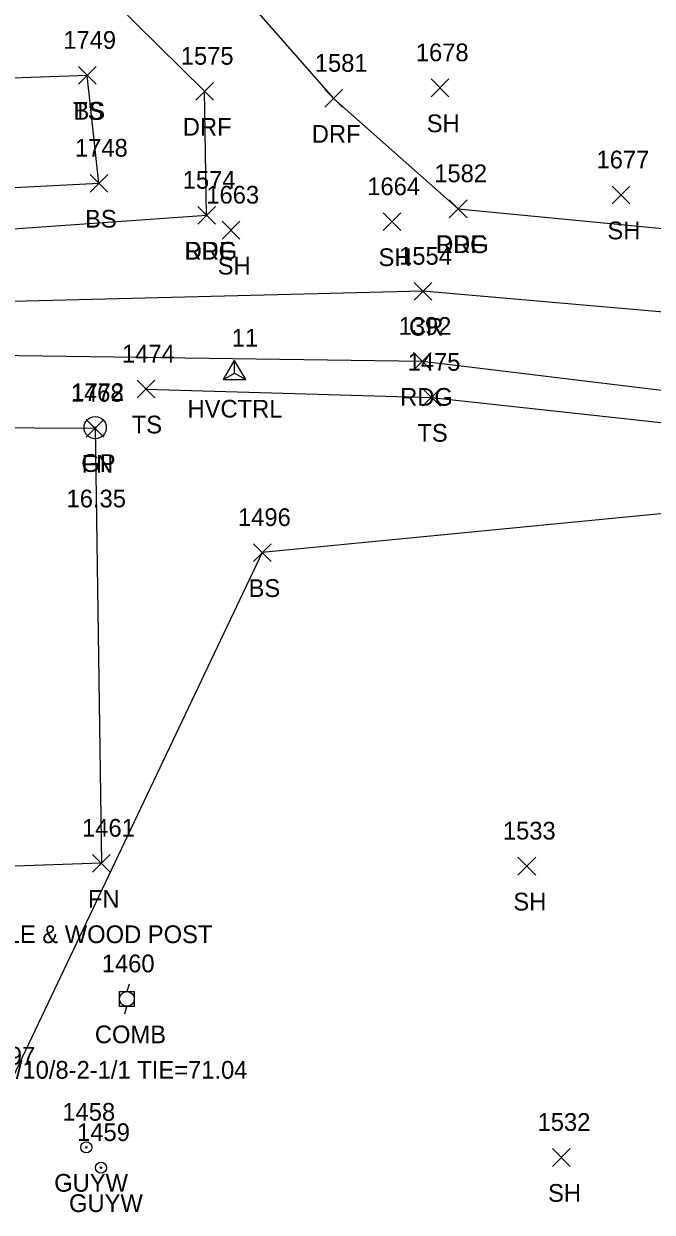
# Model space of a CAD drawing. Extents: x 1609623 to 1616187, y 756677 to 762826.
# Drawn here: x 1610243.7 to 1610314.5, y 761643.7 to 761777.7 of the extents above; entities that cross this region are included whole.
import ezdxf

# ---------------------------------------------------------------- set-up
doc = ezdxf.new("R2010")
doc.units = 0
for name, color, linetype in [('C_A', 7, 'Continuous'), ('C_I', 7, 'Continuous'), ('CPSM', 7, 'Continuous'), ('L_A', 7, 'Continuous'), ('L_C', 7, 'Continuous'), ('L_I', 7, 'Continuous'), ('L_TIC', 7, 'Continuous'), ('LELB', 7, 'Continuous'), ('LFNC', 7, 'Continuous'), ('P_A', 7, 'Continuous'), ('P_I', 7, 'Continuous'), ('P_TIC', 7, 'Continuous'), ('PEU', 7, 'Continuous'), ('PRC', 7, 'Continuous'), ('R_A', 7, 'Continuous'), ('R_C', 7, 'Continuous'), ('R_I', 7, 'Continuous'), ('R_TIC', 7, 'Continuous'), ('RDF', 7, 'Continuous'), ('RGP', 7, 'Continuous'), ('U_A', 7, 'Continuous'), ('U_C', 7, 'Continuous'), ('U_I', 7, 'Continuous'), ('UP', 7, 'Continuous'), ('UPGW', 7, 'Continuous')]:
    doc.layers.add(name, color=color, linetype=linetype)

msp = doc.modelspace()

# ---------------------------------------------------------------- linework, layer by layer
at = {"layer": 'CPSM'}
for p, q in [((1610266.22, 761737.58), (1610267.47, 761739.75)), ((1610268.72, 761737.58), (1610267.47, 761739.75)), ((1610267.47, 761738.3), (1610267.47, 761739.75)), ((1610266.22, 761737.58), (1610267.47, 761738.3)), ((1610267.47, 761738.3), (1610267.47, 761738.3)), ((1610267.47, 761738.3), (1610268.72, 761737.58)), ((1610266.22, 761737.58), (1610268.72, 761737.58))]:
    msp.add_line(p, q, dxfattribs=at)
at = {"layer": 'L_TIC'}
for points in [[(1610249.87, 761770.88), (1610251.87, 761772.88)], [(1610251.87, 761770.88), (1610249.87, 761772.88)], [(1610249.87, 761770.88), (1610251.87, 761772.88)], [(1610251.87, 761770.88), (1610249.87, 761772.88)], [(1610289.62, 761769.48), (1610291.62, 761771.48)], [(1610291.62, 761769.48), (1610289.62, 761771.48)], [(1610251.18, 761758.72), (1610253.18, 761760.72)], [(1610253.18, 761758.72), (1610251.18, 761760.72)], [(1610309.99, 761757.4), (1610311.99, 761759.4)], [(1610311.99, 761757.4), (1610309.99, 761759.4)], [(1610266.07, 761753.43), (1610268.07, 761755.43)], [(1610268.07, 761753.43), (1610266.07, 761755.43)], [(1610284.19, 761754.38), (1610286.19, 761756.38)], [(1610286.19, 761754.38), (1610284.19, 761756.38)], [(1610256.48, 761735.51), (1610258.48, 761737.51)], [(1610258.48, 761735.51), (1610256.48, 761737.51)], [(1610288.65, 761734.58), (1610290.65, 761736.58)], [(1610290.65, 761734.58), (1610288.65, 761736.58)], [(1610250.75, 761731.09), (1610252.75, 761733.09)], [(1610252.75, 761731.09), (1610250.75, 761733.09)], [(1610269.59, 761717.07), (1610271.59, 761719.07)], [(1610271.59, 761717.07), (1610269.59, 761719.07)], [(1610251.46, 761682.04), (1610253.46, 761684.04)], [(1610253.46, 761682.04), (1610251.46, 761684.04)], [(1610299.39, 761681.72), (1610301.39, 761683.72)], [(1610301.39, 761681.72), (1610299.39, 761683.72)], [(1610303.29, 761648.87), (1610305.29, 761650.87)], [(1610305.29, 761648.87), (1610303.29, 761650.87)]]:
    msp.add_lwpolyline(points, dxfattribs=at)
at = {"layer": 'LELB'}
for points in [[(1610063.27, 761768.93), (1610085.68, 761769.97), (1610116.54, 761765.89), (1610160.06, 761761.31), (1610185.8, 761758.52), (1610217.74, 761757.98), (1610252.18, 761759.72), (1610250.87, 761771.88)], [(1610250.87, 761771.88), (1610213.94, 761770.55)], [(1610257.48, 761736.51), (1610289.65, 761735.58), (1610333.79, 761730.74), (1610390.78, 761716.31), (1610438.56, 761703.45), (1610479.41, 761687.45), (1610522.96, 761672.19), (1610559.63, 761661.11), (1610576.64, 761653.22)], [(1610331.58, 761719.03), (1610334.04, 761728.28), (1610332.98, 761728.3), (1610331.88, 761725.41), (1610319.31, 761722.82), (1610270.59, 761718.07), (1610241.74, 761657.34), (1610217.07, 761660.78), (1610191.82, 761655.02), (1610167.15, 761677.06), (1610169.37, 761706.02), (1610154.67, 761706.22), (1610148.61, 761677.65)]]:
    msp.add_lwpolyline(points, dxfattribs=at)
at = {"layer": 'LFNC'}
for points in [[(1610252.46, 761683.04), (1610224.19, 761682.07), (1610182.78, 761681.45), (1610181.98, 761708.87), (1610182.24, 761715.01), (1610181.9, 761731.64), (1610217.63, 761732.3), (1610251.75, 761732.09)], [(1610251.75, 761732.09), (1610252.46, 761683.04)]]:
    msp.add_lwpolyline(points, dxfattribs=at)
at = {"layer": 'P_TIC'}
for points in [[(1610263.31, 761755.11), (1610265.31, 761757.11)], [(1610265.31, 761755.11), (1610263.31, 761757.11)], [(1610291.65, 761755.84), (1610293.65, 761757.84)], [(1610293.65, 761755.84), (1610291.65, 761757.84)], [(1610287.69, 761746.54), (1610289.69, 761748.54)], [(1610289.69, 761746.54), (1610287.69, 761748.54)], [(1610287.63, 761738.63), (1610289.63, 761740.63)], [(1610289.63, 761738.63), (1610287.63, 761740.63)]]:
    msp.add_lwpolyline(points, dxfattribs=at)
at = {"layer": 'PEU'}
for points in [[(1609803.09, 761712.98), (1609847.46, 761723.55), (1609889.39, 761733.89), (1609939.02, 761747.01), (1609990.56, 761759.58), (1610047.77, 761766.09), (1610098.04, 761763.99), (1610151.67, 761759.1), (1610189.68, 761755.64), (1610237.76, 761754.25), (1610264.31, 761756.11)], [(1610292.65, 761756.84), (1610337.52, 761752.5), (1610397.05, 761738.41), (1610444.38, 761722.79), (1610486.74, 761705.69), (1610529.9, 761690.62)], [(1610523.28, 761673.99), (1610480.04, 761689.74), (1610439, 761706.13), (1610392.08, 761720.87), (1610334.48, 761734.06), (1610288.63, 761739.63), (1610237.75, 761740.33), (1610189.36, 761741.54), (1610151.21, 761743.29), (1610095.63, 761747.13), (1610049.42, 761749.13), (1609994.68, 761742.82), (1609943, 761732.03), (1609889.61, 761718.43), (1609806.51, 761697.21)]]:
    msp.add_lwpolyline(points, dxfattribs=at)
at = {"layer": 'PRC'}
msp.add_lwpolyline([(1610601.8, 761670.75), (1610582.15, 761672.46), (1610527.05, 761683.5), (1610483.24, 761698.98), (1610440.53, 761715.33), (1610395.01, 761729.94), (1610335.18, 761743.5), (1610288.69, 761747.54), (1610237.99, 761746.29), (1610189.61, 761747.71), (1610150.7, 761750.53), (1610096.59, 761755.33), (1610048.73, 761756.09), (1609993.41, 761750.2), (1609941.26, 761738.94), (1609887.62, 761725.82), (1609805.01, 761705.08)], dxfattribs=at)
at = {"layer": 'R_TIC'}
for points in [[(1610263.09, 761769.09), (1610265.09, 761771.09)], [(1610265.09, 761769.09), (1610263.09, 761771.09)], [(1610277.62, 761768.29), (1610279.62, 761770.29)], [(1610279.62, 761768.29), (1610277.62, 761770.29)], [(1610263.31, 761755.11), (1610265.31, 761757.11)], [(1610265.31, 761755.11), (1610263.31, 761757.11)], [(1610291.65, 761755.84), (1610293.65, 761757.84)], [(1610293.65, 761755.84), (1610291.65, 761757.84)]]:
    msp.add_lwpolyline(points, dxfattribs=at)
at = {"layer": 'RDF'}
for points in [[(1610248.23, 761819.8), (1610252.09, 761803.24), (1610259.02, 761791.66), (1610278.62, 761769.29), (1610292.65, 761756.84)], [(1610264.31, 761756.11), (1610264.09, 761770.09), (1610248.38, 761785.61), (1610231.28, 761818.76)]]:
    msp.add_lwpolyline(points, dxfattribs=at)
at = {"layer": 'RGP'}
msp.add_line((1610251.76, 761732.17), (1610251.76, 761732.17), dxfattribs=at)
for radius in [1.25, 0.0833]:
    msp.add_circle((1610251.76, 761732.17), radius, dxfattribs=at)
at = {"layer": 'UP'}
for p, q in [((1610255.58, 761669.41), (1610255.33, 761668.58)), ((1610254.5, 761666.91), (1610254.5, 761668.58)), ((1610254.5, 761668.58), (1610256.16, 761668.58)), ((1610256.16, 761668.58), (1610256.16, 761666.91)), ((1610256.16, 761666.91), (1610254.5, 761666.91)), ((1610255.08, 761666.08), (1610255.33, 761666.91)), ((1610255.33, 761667.75), (1610255.33, 761667.75))]:
    msp.add_line(p, q, dxfattribs=at)
msp.add_circle((1610255.33, 761667.75), 0.833, dxfattribs=at)
at = {"layer": 'UPGW'}
for centre, radius in [((1610250.75, 761651.01), 0.625), ((1610250.75, 761651.01), 0.0833), ((1610252.42, 761648.72), 0.625), ((1610252.42, 761648.72), 0.0833)]:
    msp.add_circle(centre, radius, dxfattribs=at)

# ---------------------------------------------------------------- texts
at = {"layer": 'C_A'}
msp.add_text('HVCTRL', height=2, dxfattribs=at).set_placement((1610262.16, 761733.3))
at = {"layer": 'C_I'}
msp.add_text('11', height=2, dxfattribs=at).set_placement((1610267.14, 761741.3))
at = {"layer": 'L_A'}
for s, p in [('TS', (1610249.27, 761766.88)), ('BS', (1610249.31, 761766.88)), ('SH', (1610289.11, 761765.48)), ('BS', (1610250.62, 761754.72)), ('SH', (1610309.47, 761753.4)), ('SH', (1610265.56, 761749.43)), ('SH', (1610283.68, 761750.38)), ('TS', (1610255.88, 761731.51)), ('TS', (1610288.06, 761730.58)), ('FN', (1610250.23, 761727.09)), ('BS', (1610269.04, 761713.07)), ('FN', (1610250.94, 761678.04)), ('SH', (1610298.87, 761677.72)), ('SH', (1610302.78, 761644.87))]:
    msp.add_text(s, height=2, dxfattribs=at).set_placement(p)
at = {"layer": 'L_C'}
msp.add_text('CABLE & WOOD POST', height=2, dxfattribs=at).set_placement((1610236.29, 761674.04))
at = {"layer": 'L_I'}
for s, p in [('1749', (1610248.16, 761774.88)), ('1749', (1610248.16, 761774.88)), ('1678', (1610287.88, 761773.48)), ('1748', (1610249.48, 761762.72)), ('1677', (1610308.24, 761761.4)), ('1663', (1610264.28, 761757.43)), ('1664', (1610282.41, 761758.38)), ('1474', (1610254.78, 761739.51)), ('1475', (1610286.96, 761738.58)), ('1468', (1610249.01, 761735.09)), ('1496', (1610267.85, 761721.07)), ('1461', (1610250.28, 761686.04)), ('1533', (1610297.69, 761685.72)), ('1497', (1610239.05, 761660.34)), ('1532', (1610301.6, 761652.87))]:
    msp.add_text(s, height=2, dxfattribs=at).set_placement(p)
at = {"layer": 'P_A'}
for s, p in [('RDG', (1610290.14, 761751.84)), ('RDG', (1610261.8, 761751.11)), ('CR', (1610287.12, 761742.54)), ('RDG', (1610286.12, 761734.63))]:
    msp.add_text(s, height=2, dxfattribs=at).set_placement(p)
at = {"layer": 'P_I'}
for s, p in [('1574', (1610261.62, 761759.11)), ('1582', (1610289.96, 761759.84)), ('1554', (1610286, 761750.54)), ('1392', (1610285.94, 761742.63))]:
    msp.add_text(s, height=2, dxfattribs=at).set_placement(p)
at = {"layer": 'R_A'}
for s, p in [('DRF', (1610261.63, 761765.09)), ('DRF', (1610276.16, 761764.29)), ('DRF', (1610290.18, 761751.84)), ('DRF', (1610261.85, 761751.11)), ('GP', (1610250.19, 761727.17))]:
    msp.add_text(s, height=2, dxfattribs=at).set_placement(p)
at = {"layer": 'R_C'}
msp.add_text('16.35', height=2, dxfattribs=at).set_placement((1610248.53, 761723.17))
at = {"layer": 'R_I'}
for s, p in [('1575', (1610261.4, 761773.09)), ('1581', (1610276.5, 761772.29)), ('1574', (1610261.62, 761759.11)), ('1582', (1610289.96, 761759.84)), ('1772', (1610249.07, 761735.17))]:
    msp.add_text(s, height=2, dxfattribs=at).set_placement(p)
at = {"layer": 'U_A'}
for s, p in [('COMB', (1610251.72, 761662.75)), ('GUYW', (1610247.14, 761646.01)), ('GUYW', (1610248.81, 761643.72))]:
    msp.add_text(s, height=2, dxfattribs=at).set_placement(p)
at = {"layer": 'U_C'}
msp.add_text('#24-5/10/8-2-1/1 TIE=71.04', height=2, dxfattribs=at).set_placement((1610235.98, 761658.75))
at = {"layer": 'U_I'}
for s, p in [('1460', (1610252.5, 761670.75)), ('1458', (1610248.06, 761654.01)), ('1459', (1610249.72, 761651.72))]:
    msp.add_text(s, height=2, dxfattribs=at).set_placement(p)

doc.saveas('drawing.dxf')
